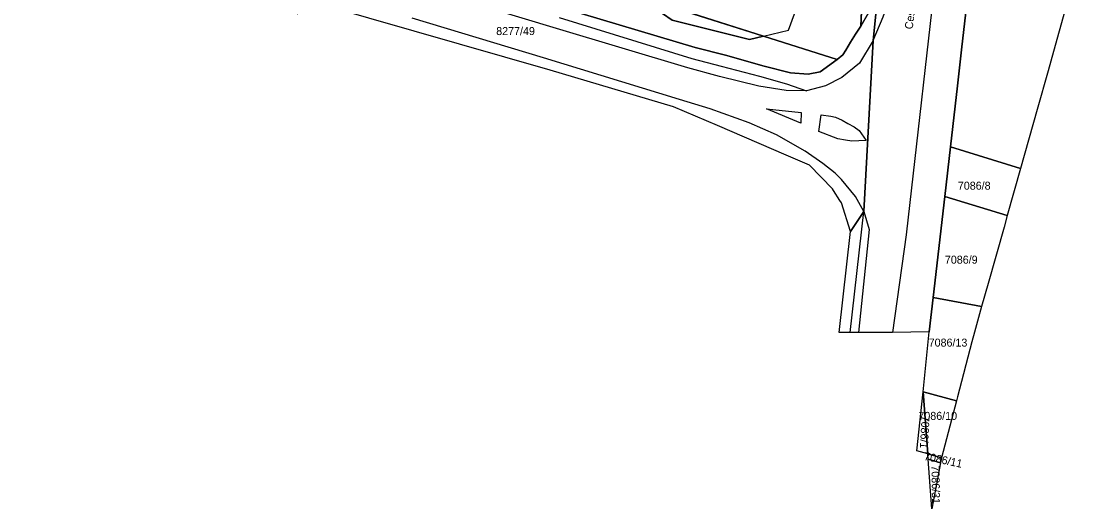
# Model space of a CAD drawing. Extents: x -266199 to -261993, y -1239047 to -1235108.
# Drawn here: x -263730.4 to -263466.2, y -1237044.1 to -1236922.3 of the extents above; entities that cross this region are included whole.
import ezdxf

# ---------------------------------------------------------------- set-up
doc = ezdxf.new("R2010")
doc.units = 0
for name, color, linetype in [('body_kn', 7, 'Continuous'), ('kladpar_druhypozemkov', 7, 'Continuous'), ('kladpar_hranice', 7, 'Continuous'), ('kladpar_parcelnecisla', 7, 'Continuous'), ('kladpar_plochy', 7, 'Continuous'), ('popisy', 7, 'Continuous'), ('zappar_hrandruhpozemk', 7, 'Continuous'), ('zuob_linie', 7, 'Continuous'), ('zuob_plochy', 7, 'Continuous')]:
    doc.layers.add(name, color=color, linetype=linetype)

msp = doc.modelspace()

# ---------------------------------------------------------------- linework, layer by layer
at = {"layer": 'body_kn'}
for p, q in [((-263596.68, -1236924.06), (-263596.68, -1236924.06)), ((-263538.72, -1236924.52), (-263538.72, -1236924.52)), ((-263522.01, -1236925.48), (-263522.01, -1236925.48)), ((-263520.64, -1236923.49), (-263520.64, -1236923.49)), ((-263520.64, -1236923.49), (-263520.64, -1236923.49)), ((-263548.45, -1236926.82), (-263548.45, -1236926.82)), ((-263544.92, -1236925.99), (-263544.92, -1236925.99)), ((-263544.92, -1236925.99), (-263544.92, -1236925.99)), ((-263523.23, -1236927.5), (-263523.23, -1236927.5)), ((-263517.52, -1236927.1), (-263517.52, -1236927.1)), ((-263517.52, -1236927.1), (-263517.52, -1236927.1)), ((-263562.06, -1236928.83), (-263562.06, -1236928.83)), ((-263554.45, -1236930.8), (-263554.45, -1236930.8)), ((-263525.15, -1236930.67), (-263525.15, -1236930.67)), ((-263524.42, -1236929.5), (-263524.42, -1236929.5)), ((-263495.46, -1236929.4), (-263495.46, -1236929.4)), ((-263472.5, -1236929.85), (-263472.5, -1236929.85)), ((-263599.88, -1236931.46), (-263599.88, -1236931.46)), ((-263562.84, -1236931.6), (-263562.84, -1236931.6)), ((-263544.76, -1236933.48), (-263544.76, -1236933.48)), ((-263526.53, -1236931.83), (-263526.53, -1236931.83)), ((-263521.01, -1236932.79), (-263521.01, -1236932.79)), ((-263598.26, -1236934.52), (-263598.26, -1236934.52)), ((-263563.87, -1236933.94), (-263563.87, -1236933.94)), ((-263555.91, -1236936.11), (-263555.91, -1236936.11)), ((-263555.53, -1236933.49), (-263555.53, -1236933.49)), ((-263545.94, -1236935.99), (-263545.94, -1236935.99)), ((-263538.17, -1236935.17), (-263538.17, -1236935.17)), ((-263533.8, -1236935.53), (-263533.8, -1236935.53)), ((-263530.81, -1236934.92), (-263530.81, -1236934.92)), ((-263473.87, -1236934.71), (-263473.87, -1236934.71)), ((-263546.09, -1236938.51), (-263546.09, -1236938.51)), ((-263539.2, -1236937.89), (-263539.2, -1236937.89)), ((-263539.2, -1236937.89), (-263539.2, -1236937.89)), ((-263529.43, -1236938.44), (-263529.43, -1236938.44)), ((-263525.41, -1236936.33), (-263525.41, -1236936.33)), ((-263496.5, -1236938.41), (-263496.5, -1236938.41)), ((-263539.25, -1236939.59), (-263539.25, -1236939.59)), ((-263534.23, -1236939.68), (-263534.23, -1236939.68)), ((-263567.43, -1236943.68), (-263567.43, -1236943.68)), ((-263565.92, -1236941.82), (-263565.92, -1236941.82)), ((-263558.26, -1236944.2), (-263558.26, -1236944.2)), ((-263544.19, -1236944.15), (-263544.19, -1236944.15)), ((-263535.53, -1236945.06), (-263535.53, -1236945.06)), ((-263535.53, -1236945.06), (-263535.53, -1236945.06)), ((-263530.53, -1236945.71), (-263530.53, -1236945.71)), ((-263530.53, -1236945.71), (-263530.53, -1236945.71)), ((-263528.14, -1236946), (-263528.14, -1236946)), ((-263526.93, -1236946.29), (-263526.93, -1236946.29)), ((-263476.6, -1236944.38), (-263476.6, -1236944.38)), ((-263556.44, -1236948.35), (-263556.44, -1236948.35)), ((-263548.52, -1236947.69), (-263548.52, -1236947.69)), ((-263535.65, -1236947.79), (-263535.65, -1236947.79)), ((-263525.26, -1236947.04), (-263525.26, -1236947.04)), ((-263523.86, -1236947.8), (-263523.86, -1236947.8)), ((-263522.29, -1236948.71), (-263522.29, -1236948.71)), ((-263541.72, -1236950.68), (-263541.72, -1236950.68)), ((-263531.13, -1236949.82), (-263531.13, -1236949.82)), ((-263526.35, -1236951.67), (-263526.35, -1236951.67)), ((-263524.5, -1236951.97), (-263524.5, -1236951.97)), ((-263521.08, -1236949.59), (-263521.08, -1236949.59)), ((-263522.87, -1236952.22), (-263522.87, -1236952.22)), ((-263521.12, -1236952.17), (-263521.12, -1236952.17)), ((-263519.27, -1236952.07), (-263519.27, -1236952.07)), ((-263498.25, -1236953.68), (-263498.25, -1236953.68)), ((-263539.31, -1236955.76), (-263539.31, -1236955.76)), ((-263534.56, -1236954.74), (-263534.56, -1236954.74)), ((-263533.48, -1236958.28), (-263533.48, -1236958.28)), ((-263530.11, -1236957.84), (-263530.11, -1236957.84)), ((-263480.74, -1236959.12), (-263480.74, -1236959.12)), ((-263527.07, -1236960.29), (-263527.07, -1236960.29)), ((-263525.48, -1236961.79), (-263525.48, -1236961.79)), ((-263527.7, -1236964.14), (-263527.7, -1236964.14)), ((-263527.45, -1236964.54), (-263527.45, -1236964.54)), ((-263525.85, -1236967.05), (-263525.85, -1236967.05)), ((-263525.44, -1236967.7), (-263525.44, -1236967.7)), ((-263521.94, -1236966.09), (-263521.94, -1236966.09)), ((-263499.67, -1236966.08), (-263499.67, -1236966.08)), ((-263519.86, -1236969.84), (-263519.86, -1236969.84)), ((-263519.86, -1236969.84), (-263519.86, -1236969.84)), ((-263484.04, -1236970.83), (-263484.04, -1236970.83)), ((-263484.04, -1236970.83), (-263484.04, -1236970.83)), ((-263523.24, -1236974.84), (-263523.24, -1236974.84)), ((-263518.59, -1236974.33), (-263518.59, -1236974.33)), ((-263509.32, -1236975.64), (-263509.32, -1236975.64)), ((-263484.86, -1236973.73), (-263484.86, -1236973.73)), ((-263488.83, -1236987.84), (-263488.83, -1236987.84)), ((-263502.57, -1236991.35), (-263502.57, -1236991.35)), ((-263502.57, -1236991.35), (-263502.57, -1236991.35)), ((-263490.45, -1236993.6), (-263490.45, -1236993.6)), ((-263490.45, -1236993.6), (-263490.45, -1236993.6)), ((-263526.08, -1237000.08), (-263526.08, -1237000.08)), ((-263526.08, -1237000.08), (-263526.08, -1237000.08)), ((-263523.26, -1237000.07), (-263523.26, -1237000.07)), ((-263523.26, -1237000.07), (-263523.26, -1237000.07)), ((-263521.24, -1237000.04), (-263521.24, -1237000.04)), ((-263512.75, -1237000.05), (-263512.75, -1237000.05)), ((-263503.55, -1236999.93), (-263503.55, -1236999.93)), ((-263492.25, -1236999.99), (-263492.25, -1236999.99)), ((-263492.89, -1237002.42), (-263492.89, -1237002.42)), ((-263505.09, -1237014.85), (-263505.09, -1237014.85)), ((-263505.09, -1237014.85), (-263505.09, -1237014.85)), ((-263496.75, -1237017.1), (-263496.75, -1237017.1)), ((-263496.5, -1237016.13), (-263496.5, -1237016.13)), ((-263506.62, -1237029.64), (-263506.62, -1237029.64)), ((-263503.92, -1237030.41), (-263503.92, -1237030.41)), ((-263503.82, -1237031.71), (-263503.82, -1237031.71)), ((-263503.82, -1237031.71), (-263503.82, -1237031.71)), ((-263500.73, -1237032.59), (-263500.73, -1237032.59)), ((-263500.73, -1237032.59), (-263500.73, -1237032.59)), ((-263500.5, -1237031.39), (-263500.5, -1237031.39)), ((-263502.89, -1237044.13), (-263502.89, -1237044.13))]:
    msp.add_line(p, q, dxfattribs=at)
at = {"layer": 'kladpar_druhypozemkov'}
for p, q in [((-263606.46, -1236924.16), (-263606.46, -1236924.16)), ((-263491.56, -1236962.35), (-263491.56, -1236962.35)), ((-263494.86, -1236980.87), (-263494.86, -1236980.87)), ((-263497.64, -1237001.43), (-263497.64, -1237001.43)), ((-263500.95, -1237019.75), (-263500.95, -1237019.75)), ((-263505.64, -1237021.07), (-263505.64, -1237021.07)), ((-263502.64, -1237031.18), (-263502.64, -1237031.18)), ((-263502.37, -1237034.62), (-263502.37, -1237034.62))]:
    msp.add_line(p, q, dxfattribs=at)
at = {"layer": 'kladpar_hranice'}
msp.add_line((-263544.92, -1236925.99), (-263526.53, -1236931.83), dxfattribs=at)
for points in [[(-263526.08, -1237000.08), (-263523.24, -1236974.84), (-263519.86, -1236969.84), (-263517.52, -1236927.1), (-263515.05, -1236902.26), (-263514.5, -1236897.94), (-263510.2, -1236861.98), (-263504.89, -1236815.91), (-263504.7, -1236814.24), (-263504.13, -1236809.2), (-263501.6, -1236788.9), (-263501, -1236779.03), (-263500.82, -1236772.21), (-263500.8, -1236753.8), (-263501.38, -1236742.95), (-263503.08, -1236727.74), (-263503.49, -1236725.48), (-263504.1, -1236722.15), (-263504.33, -1236720.87), (-263504.42, -1236720.38), (-263509.9, -1236696.81), (-263510.21, -1236695.48), (-263510.88, -1236692.59), (-263516.42, -1236668.71)], [(-263509.65, -1236808.55), (-263509.62, -1236813.31), (-263509.61, -1236814.84), (-263509.59, -1236817.96), (-263509.47, -1236835.23), (-263512.51, -1236836.48), (-263516.79, -1236838.25), (-263518.48, -1236875.69), (-263519.42, -1236896.41), (-263519.62, -1236900.98), (-263520.64, -1236923.49), (-263522.01, -1236925.48), (-263523.23, -1236927.5), (-263524.42, -1236929.5), (-263525.15, -1236930.67), (-263526.53, -1236931.83)], [(-263504.13, -1236809.2), (-263504.7, -1236814.24), (-263504.89, -1236815.91), (-263510.2, -1236861.98), (-263514.5, -1236897.94), (-263515.05, -1236902.26), (-263516.4, -1236911.92), (-263518.7, -1236920.21), (-263520.64, -1236923.49)], [(-263484.84, -1236836.77), (-263486.71, -1236853.09), (-263486.96, -1236855.29), (-263488.24, -1236866.5), (-263488.72, -1236870.67), (-263489.2, -1236874.82), (-263492.06, -1236899.71), (-263495.46, -1236929.4), (-263496.5, -1236938.41), (-263498.25, -1236953.68), (-263499.67, -1236966.08), (-263502.57, -1236991.35), (-263503.55, -1236999.93), (-263512.75, -1237000.05), (-263521.24, -1237000.04), (-263523.26, -1237000.07), (-263526.08, -1237000.08)], [(-263737.21, -1236847.24), (-263728.66, -1236852.26), (-263724.24, -1236852.11), (-263723.45, -1236852.13), (-263724.23, -1236854.5), (-263697.93, -1236874.68), (-263690.23, -1236880.72), (-263684.19, -1236885.23), (-263677.59, -1236889.83), (-263671.4, -1236893.24), (-263664.84, -1236896.35), (-263662.73, -1236897.18), (-263659.89, -1236898.97), (-263654.07, -1236900.91), (-263648.55, -1236902.77), (-263629.21, -1236908.64), (-263595.25, -1236918.92), (-263562.06, -1236928.83), (-263554.45, -1236930.8), (-263544.76, -1236933.48), (-263538.17, -1236935.17), (-263533.8, -1236935.53), (-263530.81, -1236934.92), (-263526.53, -1236931.83)], [(-263724.23, -1236854.5), (-263723.45, -1236852.13), (-263718.46, -1236856.19), (-263688.65, -1236880.45), (-263667.08, -1236892.65), (-263664.39, -1236893.76), (-263661.55, -1236895.1), (-263658.75, -1236896.43), (-263603.79, -1236911.79), (-263599.38, -1236913.98), (-263570.2, -1236920.36), (-263567.73, -1236922.05), (-263548.45, -1236926.82), (-263544.92, -1236925.99)], [(-263526.53, -1236931.83), (-263530.81, -1236934.92), (-263533.8, -1236935.53), (-263538.17, -1236935.17), (-263544.76, -1236933.48), (-263554.45, -1236930.8), (-263562.06, -1236928.83), (-263595.25, -1236918.92), (-263629.21, -1236908.64), (-263648.55, -1236902.77), (-263654.07, -1236900.91), (-263659.89, -1236898.97), (-263662.73, -1236897.18), (-263664.84, -1236896.35), (-263671.4, -1236893.24), (-263677.59, -1236889.83), (-263684.19, -1236885.23), (-263690.23, -1236880.72), (-263697.93, -1236874.68), (-263724.23, -1236854.5)], [(-263520.64, -1236923.49), (-263519.62, -1236900.98), (-263519.42, -1236896.41), (-263518.48, -1236875.69)], [(-263544.92, -1236925.99), (-263548.45, -1236926.82), (-263567.73, -1236922.05), (-263570.2, -1236920.36), (-263599.38, -1236913.98), (-263603.79, -1236911.79), (-263658.75, -1236896.43), (-263661.55, -1236895.1), (-263659.67, -1236888.98)], [(-263659.67, -1236888.98), (-263628.3, -1236899.21), (-263625.92, -1236899.99), (-263602.57, -1236907.6), (-263599.02, -1236908.76), (-263594.85, -1236910.12), (-263584.48, -1236913.42), (-263544.92, -1236925.99)], [(-263466.17, -1236907.33), (-263468.63, -1236916.06), (-263472.5, -1236929.85), (-263473.87, -1236934.71), (-263476.6, -1236944.38), (-263480.74, -1236959.12), (-263498.25, -1236953.68), (-263496.5, -1236938.41), (-263495.46, -1236929.4), (-263492.06, -1236899.71), (-263478.58, -1236903.68), (-263466.17, -1236907.33)], [(-263520.64, -1236923.49), (-263518.7, -1236920.21), (-263516.4, -1236911.92), (-263515.05, -1236902.26), (-263517.52, -1236927.1), (-263519.86, -1236969.84), (-263523.24, -1236974.84), (-263525.44, -1236967.7), (-263525.85, -1236967.05), (-263527.45, -1236964.54), (-263527.7, -1236964.14), (-263533.48, -1236958.28), (-263539.31, -1236955.76), (-263556.44, -1236948.35), (-263567.43, -1236943.68), (-263598.26, -1236934.52), (-263654.92, -1236918.23), (-263659.33, -1236917.75), (-263661.52, -1236920.5)], [(-263526.53, -1236931.83), (-263544.92, -1236925.99), (-263584.48, -1236913.42), (-263594.85, -1236910.12), (-263599.02, -1236908.76), (-263582.4, -1236904.03)], [(-263526.53, -1236931.83), (-263525.15, -1236930.67), (-263524.42, -1236929.5), (-263523.23, -1236927.5), (-263522.01, -1236925.48), (-263520.64, -1236923.49)], [(-263484.04, -1236970.83), (-263499.67, -1236966.08), (-263498.25, -1236953.68), (-263480.74, -1236959.12), (-263484.04, -1236970.83)], [(-263490.45, -1236993.6), (-263502.57, -1236991.35), (-263499.67, -1236966.08), (-263484.04, -1236970.83), (-263484.86, -1236973.73), (-263488.83, -1236987.84), (-263490.45, -1236993.6)], [(-263502.57, -1236991.35), (-263490.45, -1236993.6), (-263492.25, -1236999.99), (-263492.89, -1237002.42), (-263496.5, -1237016.13), (-263496.75, -1237017.1), (-263505.09, -1237014.85), (-263503.55, -1236999.93), (-263502.57, -1236991.35)], [(-263505.09, -1237014.85), (-263503.92, -1237030.41), (-263506.62, -1237029.64), (-263505.09, -1237014.85)], [(-263505.09, -1237014.85), (-263496.75, -1237017.1), (-263500.5, -1237031.39), (-263503.92, -1237030.41), (-263505.09, -1237014.85)], [(-263503.82, -1237031.71), (-263503.92, -1237030.41), (-263500.5, -1237031.39), (-263500.73, -1237032.59), (-263503.82, -1237031.71)], [(-263500.73, -1237032.59), (-263502.89, -1237044.13), (-263503.82, -1237031.71), (-263500.73, -1237032.59)]]:
    msp.add_lwpolyline(points, dxfattribs=at)
at = {"layer": 'kladpar_plochy'}
for p, q in [((-263519.62, -1236900.98), (-263520.64, -1236923.49)), ((-263544.92, -1236925.99), (-263584.48, -1236913.42)), ((-263522.01, -1236925.48), (-263523.23, -1236927.5)), ((-263520.64, -1236923.49), (-263522.01, -1236925.48)), ((-263526.53, -1236931.83), (-263544.92, -1236925.99)), ((-263523.23, -1236927.5), (-263524.42, -1236929.5)), ((-263525.15, -1236930.67), (-263526.53, -1236931.83)), ((-263524.42, -1236929.5), (-263525.15, -1236930.67))]:
    msp.add_line(p, q, dxfattribs=at)
for points in [[(-263504.13, -1236809.2), (-263504.7, -1236814.24), (-263504.89, -1236815.91), (-263510.2, -1236861.98), (-263514.5, -1236897.94), (-263515.05, -1236902.26), (-263516.4, -1236911.92), (-263518.7, -1236920.21), (-263520.64, -1236923.49), (-263519.62, -1236900.98), (-263519.42, -1236896.41), (-263518.48, -1236875.69), (-263516.01, -1236858.67), (-263512.51, -1236836.48), (-263509.47, -1236835.23), (-263509.59, -1236817.96), (-263509.11, -1236814.95), (-263508.87, -1236813.41), (-263508.05, -1236808.68)], [(-263659.67, -1236888.98), (-263628.3, -1236899.21), (-263625.92, -1236899.99), (-263602.57, -1236907.6), (-263599.02, -1236908.76), (-263594.85, -1236910.12), (-263584.48, -1236913.42), (-263544.92, -1236925.99), (-263548.45, -1236926.82), (-263567.73, -1236922.05), (-263570.2, -1236920.36), (-263599.38, -1236913.98), (-263603.79, -1236911.79), (-263658.75, -1236896.43), (-263661.55, -1236895.1)], [(-263466.17, -1236907.33), (-263468.63, -1236916.06), (-263472.5, -1236929.85), (-263473.87, -1236934.71), (-263476.6, -1236944.38), (-263480.74, -1236959.12), (-263498.25, -1236953.68), (-263496.5, -1236938.41), (-263495.46, -1236929.4), (-263492.06, -1236899.71), (-263478.58, -1236903.68)], [(-263484.04, -1236970.83), (-263499.67, -1236966.08), (-263498.25, -1236953.68), (-263480.74, -1236959.12)], [(-263490.45, -1236993.6), (-263502.57, -1236991.35), (-263499.67, -1236966.08), (-263484.04, -1236970.83), (-263484.86, -1236973.73), (-263488.83, -1236987.84)], [(-263502.57, -1236991.35), (-263490.45, -1236993.6), (-263492.25, -1236999.99), (-263492.89, -1237002.42), (-263496.5, -1237016.13), (-263496.75, -1237017.1), (-263505.09, -1237014.85), (-263503.55, -1236999.93)], [(-263505.09, -1237014.85), (-263503.92, -1237030.41), (-263506.62, -1237029.64)], [(-263505.09, -1237014.85), (-263496.75, -1237017.1), (-263500.5, -1237031.39), (-263503.92, -1237030.41)], [(-263503.82, -1237031.71), (-263503.92, -1237030.41), (-263500.5, -1237031.39), (-263500.73, -1237032.59)], [(-263500.73, -1237032.59), (-263502.89, -1237044.13), (-263503.82, -1237031.71)]]:
    msp.add_lwpolyline(points, close=True, dxfattribs=at)
for points in [[(-263492.06, -1236899.71), (-263495.46, -1236929.4), (-263496.5, -1236938.41), (-263498.25, -1236953.68), (-263499.67, -1236966.08), (-263502.57, -1236991.35), (-263503.55, -1236999.93), (-263512.75, -1237000.05), (-263521.24, -1237000.04), (-263523.26, -1237000.07), (-263526.08, -1237000.08), (-263523.24, -1236974.84), (-263519.86, -1236969.84), (-263517.52, -1236927.1), (-263515.05, -1236902.26)], [(-263515.05, -1236902.26), (-263517.52, -1236927.1), (-263519.86, -1236969.84), (-263523.24, -1236974.84), (-263525.44, -1236967.7), (-263525.85, -1236967.05), (-263527.45, -1236964.54), (-263527.7, -1236964.14), (-263533.48, -1236958.28), (-263539.31, -1236955.76), (-263556.44, -1236948.35), (-263567.43, -1236943.68), (-263598.26, -1236934.52), (-263654.92, -1236918.23)], [(-263595.25, -1236918.92), (-263562.06, -1236928.83), (-263554.45, -1236930.8), (-263544.76, -1236933.48), (-263538.17, -1236935.17), (-263533.8, -1236935.53), (-263530.81, -1236934.92), (-263526.53, -1236931.83), (-263525.15, -1236930.67), (-263524.42, -1236929.5), (-263523.23, -1236927.5), (-263522.01, -1236925.48), (-263520.64, -1236923.49), (-263518.7, -1236920.21)], [(-263567.73, -1236922.05), (-263548.45, -1236926.82), (-263544.92, -1236925.99), (-263526.53, -1236931.83), (-263530.81, -1236934.92), (-263533.8, -1236935.53), (-263538.17, -1236935.17), (-263544.76, -1236933.48), (-263554.45, -1236930.8), (-263562.06, -1236928.83), (-263595.25, -1236918.92)]]:
    msp.add_lwpolyline(points, dxfattribs=at)
at = {"layer": 'zappar_hrandruhpozemk'}
for p, q in [((-263538.72, -1236924.52), (-263530.13, -1236901.31)), ((-263596.68, -1236924.06), (-263631.01, -1236913.72)), ((-263599.88, -1236931.46), (-263632.76, -1236921.51)), ((-263596.04, -1236921.39), (-263562.84, -1236931.6)), ((-263544.92, -1236925.99), (-263538.72, -1236924.52)), ((-263546.09, -1236938.51), (-263555.91, -1236936.11)), ((-263529.43, -1236938.44), (-263534.23, -1236939.68)), ((-263525.41, -1236936.33), (-263529.43, -1236938.44)), ((-263535.53, -1236945.06), (-263535.65, -1236947.79)), ((-263531.13, -1236949.82), (-263530.53, -1236945.71)), ((-263534.56, -1236954.74), (-263541.72, -1236950.68)), ((-263523.26, -1237000.07), (-263519.86, -1236969.84)), ((-263519.86, -1236969.84), (-263518.59, -1236974.33)), ((-263518.59, -1236974.33), (-263521.24, -1237000.04)), ((-263509.32, -1236975.64), (-263512.75, -1237000.05))]:
    msp.add_line(p, q, dxfattribs=at)
for points in [[(-263493.02, -1236836.2), (-263501.22, -1236904.42), (-263509.32, -1236975.64)], [(-263517.52, -1236927.1), (-263515.07, -1236921.18), (-263514.49, -1236919.63)], [(-263555.91, -1236936.11), (-263563.87, -1236933.94), (-263596.68, -1236924.06)], [(-263517.52, -1236927.1), (-263521.01, -1236932.79), (-263525.41, -1236936.33)], [(-263541.72, -1236950.68), (-263548.52, -1236947.69), (-263558.26, -1236944.2), (-263565.92, -1236941.82), (-263599.88, -1236931.46)], [(-263562.84, -1236931.6), (-263555.53, -1236933.49), (-263545.94, -1236935.99), (-263539.2, -1236937.89)], [(-263539.2, -1236937.89), (-263534.23, -1236939.68), (-263539.25, -1236939.59), (-263546.09, -1236938.51)], [(-263535.65, -1236947.79), (-263544.19, -1236944.15), (-263535.53, -1236945.06)], [(-263530.53, -1236945.71), (-263528.14, -1236946), (-263526.93, -1236946.29), (-263525.26, -1236947.04), (-263523.86, -1236947.8), (-263522.29, -1236948.71), (-263521.08, -1236949.59), (-263519.27, -1236952.07), (-263521.12, -1236952.17), (-263522.87, -1236952.22), (-263524.5, -1236951.97), (-263526.35, -1236951.67), (-263531.13, -1236949.82)], [(-263519.86, -1236969.84), (-263521.94, -1236966.09), (-263525.48, -1236961.79), (-263527.07, -1236960.29), (-263530.11, -1236957.84), (-263534.56, -1236954.74)]]:
    msp.add_lwpolyline(points, dxfattribs=at)
at = {"layer": 'zuob_linie'}
msp.add_lwpolyline([(-263468.63, -1236916.06), (-263472.5, -1236929.85), (-263473.87, -1236934.71), (-263476.6, -1236944.38), (-263480.74, -1236959.12), (-263484.04, -1236970.83), (-263484.86, -1236973.73), (-263488.83, -1236987.84), (-263490.45, -1236993.6), (-263492.25, -1236999.99), (-263492.89, -1237002.42), (-263496.5, -1237016.13), (-263496.75, -1237017.1), (-263500.5, -1237031.39), (-263500.73, -1237032.59), (-263502.89, -1237044.13), (-263503.82, -1237031.71), (-263503.92, -1237030.41), (-263506.62, -1237029.64), (-263505.09, -1237014.85), (-263503.55, -1236999.93), (-263512.75, -1237000.05), (-263521.24, -1237000.04), (-263523.26, -1237000.07), (-263526.08, -1237000.08), (-263523.24, -1236974.84), (-263525.44, -1236967.7), (-263525.85, -1236967.05), (-263527.45, -1236964.54), (-263527.7, -1236964.14), (-263533.48, -1236958.28), (-263539.31, -1236955.76), (-263556.44, -1236948.35), (-263567.43, -1236943.68), (-263598.26, -1236934.52), (-263654.92, -1236918.23)], dxfattribs=at)
at = {"layer": 'zuob_plochy'}
msp.add_lwpolyline([(-263468.63, -1236916.06), (-263472.5, -1236929.85), (-263473.87, -1236934.71), (-263476.6, -1236944.38), (-263480.74, -1236959.12), (-263484.04, -1236970.83), (-263484.86, -1236973.73), (-263488.83, -1236987.84), (-263490.45, -1236993.6), (-263492.25, -1236999.99), (-263492.89, -1237002.42), (-263496.5, -1237016.13), (-263496.75, -1237017.1), (-263500.5, -1237031.39), (-263500.73, -1237032.59), (-263502.89, -1237044.13), (-263503.82, -1237031.71), (-263503.92, -1237030.41), (-263506.62, -1237029.64), (-263505.09, -1237014.85), (-263503.55, -1236999.93), (-263512.75, -1237000.05), (-263521.24, -1237000.04), (-263523.26, -1237000.07), (-263526.08, -1237000.08), (-263523.24, -1236974.84), (-263525.44, -1236967.7), (-263525.85, -1236967.05), (-263527.45, -1236964.54), (-263527.7, -1236964.14), (-263533.48, -1236958.28), (-263539.31, -1236955.76), (-263556.44, -1236948.35), (-263567.43, -1236943.68), (-263598.26, -1236934.52), (-263654.92, -1236918.23)], dxfattribs=at)

# ---------------------------------------------------------------- texts
at = {"layer": 'kladpar_parcelnecisla'}
for s, p in [('8277/49', (-263611.73, -1236925.74)), ('7086/8', (-263496.4, -1236964.38)), ('7086/9', (-263499.64, -1236982.87)), ('7086/13', (-263503.69, -1237003.59)), ('7086/10', (-263506.26, -1237021.9))]:
    msp.add_text(s, height=2, dxfattribs=at).set_placement(p)
for s, rotation, p in [('7086/1', 267, (-263505.45, -1237020.81)), ('7086/11', 348, (-263504.97, -1237031.88)), ('7086/31', 271, (-263503, -1237033.28))]:
    msp.add_text(s, height=2, rotation=rotation, dxfattribs=at).set_placement(p)
at = {"layer": 'popisy'}
msp.add_text('Cesta pod Hradovou', height=2, rotation=82, dxfattribs=at).set_placement((-263507.73, -1236924.39))

doc.saveas('drawing.dxf')
